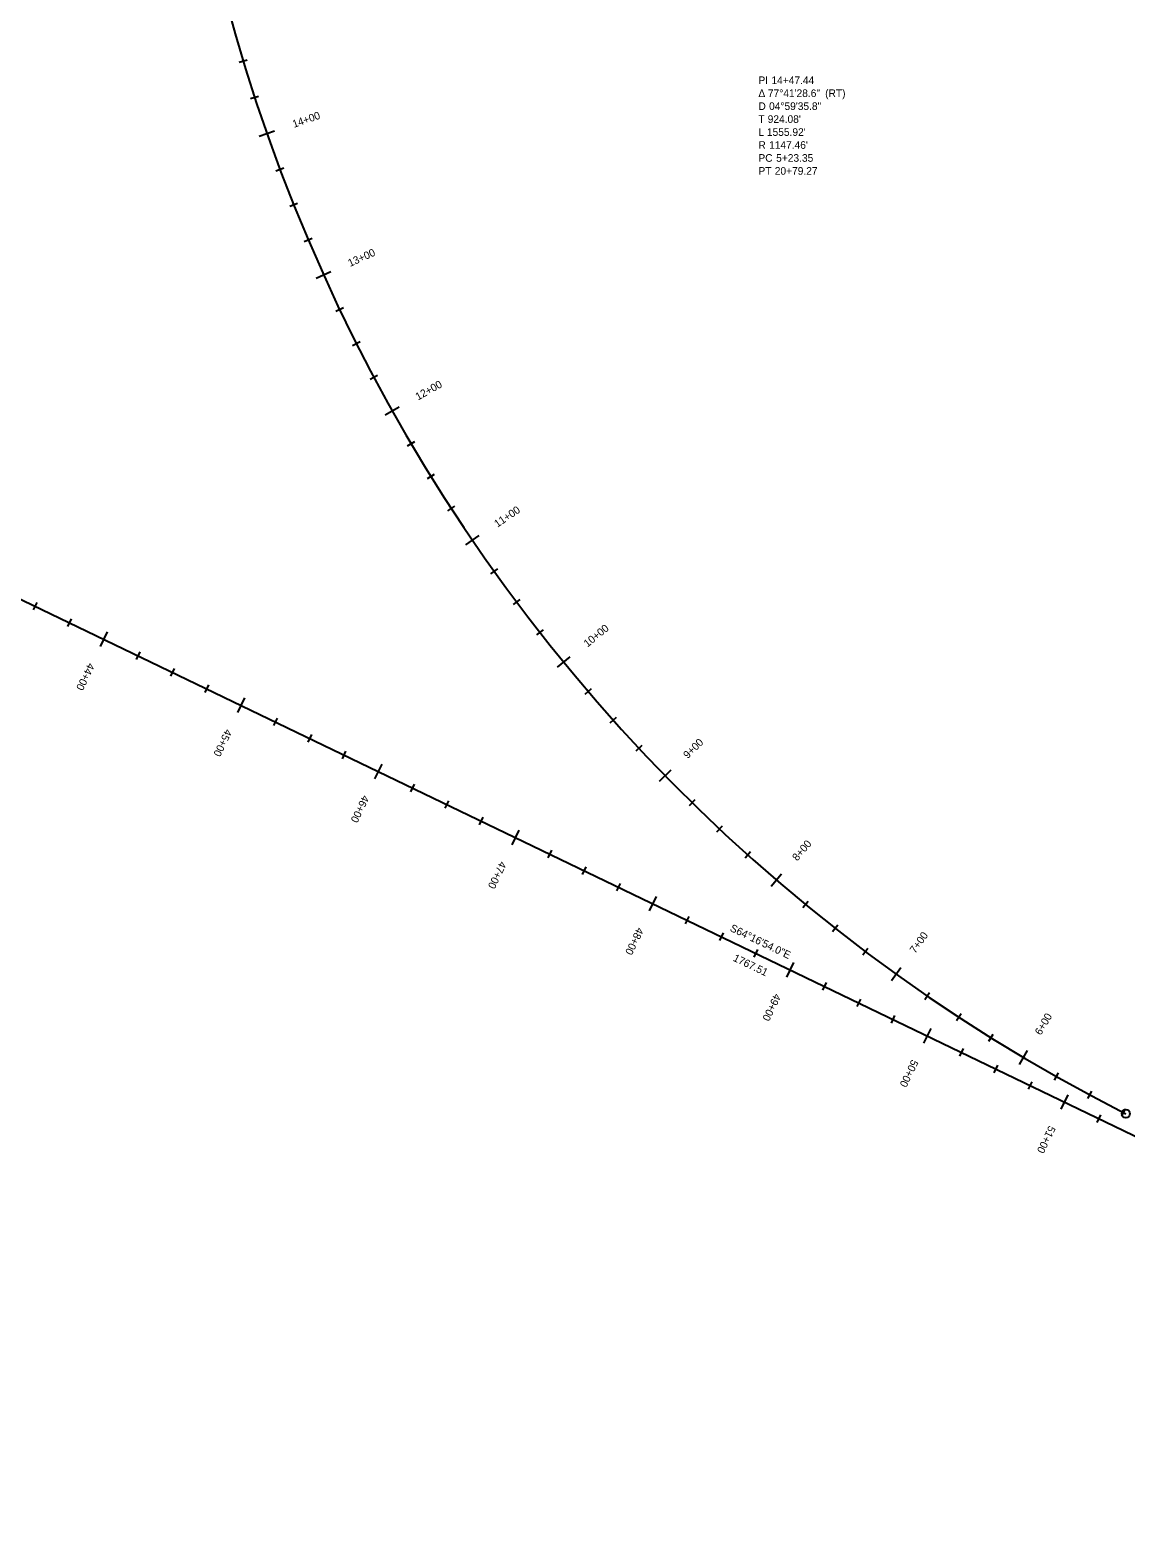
# Model space of a CAD drawing. Extents: x 2300830 to 2307917, y 756066 to 766359.
# Drawn here: x 2304246 to 2304965, y 761142 to 762132 of the extents above; entities that cross this region are included whole.
import ezdxf

# ---------------------------------------------------------------- set-up
doc = ezdxf.new("R2010")
doc.units = 0
for name, color, linetype in [('Default', 7, 'Continuous'), ('Draft_Bearing Label', 7, 'Continuous'), ('Draft_Curve Data Label', 7, 'Continuous'), ('Draft_Station Cardinal Points', 7, 'Continuous'), ('Draft_Station Labels Major', 7, 'Continuous'), ('Draft_Station Ticks Major', 7, 'Continuous'), ('Draft_Station Ticks Minor', 7, 'Continuous'), ('Geom_Baseline', 7, 'Continuous')]:
    doc.layers.add(name, color=color, linetype=linetype)

msp = doc.modelspace()

# ---------------------------------------------------------------- linework, layer by layer
at = {"layer": 'Default'}
msp.add_line((2303926.45, 761909.44), (2305518.87, 761142.43), dxfattribs=at)
for centre, radius, start, end in [((2294501.04, 766942.01), 10544.55, 331.835697, 340.516399), ((2305484.17, 762444.28), 1147.46, 165.42872, 243.12)]:
    msp.add_arc(centre, radius, start, end, dxfattribs=at)
at = {"layer": 'Draft_Station Cardinal Points'}
msp.add_line((2304965.38, 761420.8), (2304965.38, 761420.8), dxfattribs=at)
msp.add_circle((2304965.38, 761420.8), 2.67, dxfattribs=at)
at = {"layer": 'Draft_Station Ticks Major'}
for p, q in [((2304396.47, 762062.39), (2304406.49, 762065.9)), ((2304433.83, 761969.16), (2304443.51, 761973.54)), ((2304479.17, 761879.55), (2304488.43, 761884.75)), ((2304532.14, 761794.22), (2304540.91, 761800.2)), ((2304296.7, 761737.03), (2304292.09, 761727.46)), ((2304592.34, 761713.82), (2304600.55, 761720.55)), ((2304386.79, 761693.63), (2304382.18, 761684.07)), ((2304476.89, 761650.24), (2304472.28, 761640.67)), ((2304659.3, 761638.97), (2304666.9, 761646.39)), ((2304566.98, 761606.85), (2304562.37, 761597.28)), ((2304732.52, 761570.23), (2304739.45, 761578.28)), ((2304657.07, 761563.45), (2304652.47, 761553.88)), ((2304747.17, 761520.06), (2304742.56, 761510.49)), ((2304811.45, 761508.12), (2304817.65, 761516.75)), ((2304837.26, 761476.66), (2304832.65, 761467.09)), ((2304895.49, 761453.12), (2304900.91, 761462.25)), ((2304927.36, 761433.27), (2304922.75, 761423.7))]:
    msp.add_line(p, q, dxfattribs=at)
at = {"layer": 'Draft_Station Ticks Minor'}
for p, q in [((2304383.33, 762110.88), (2304388.62, 762112.48)), ((2304390.86, 762086.97), (2304396.1, 762088.69)), ((2304407.46, 762039.69), (2304412.63, 762041.63)), ((2304416.53, 762016.33), (2304421.65, 762018.38)), ((2304426.11, 761993.17), (2304431.18, 761995.33)), ((2304446.76, 761947.51), (2304451.74, 761949.89)), ((2304457.83, 761925.03), (2304462.76, 761927.52)), ((2304469.39, 761902.79), (2304474.26, 761905.39)), ((2304493.94, 761859.1), (2304498.69, 761861.91)), ((2304506.92, 761837.66), (2304511.61, 761840.58)), ((2304520.37, 761816.52), (2304524.99, 761819.53)), ((2304548.63, 761775.13), (2304553.12, 761778.34)), ((2304563.43, 761754.91), (2304567.85, 761758.22)), ((2304250.53, 761756.4), (2304248.14, 761751.43)), ((2304273.06, 761745.55), (2304270.66, 761740.58)), ((2304578.67, 761735.01), (2304583.01, 761738.42)), ((2304318.1, 761723.86), (2304315.71, 761718.88)), ((2304340.63, 761713.01), (2304338.23, 761708.03)), ((2304363.15, 761702.16), (2304360.75, 761697.19)), ((2304610.42, 761696.24), (2304614.62, 761699.83)), ((2304408.2, 761680.46), (2304405.8, 761675.49)), ((2304626.93, 761677.38), (2304631.04, 761681.06)), ((2304430.72, 761669.61), (2304428.33, 761664.64)), ((2304453.24, 761658.76), (2304450.85, 761653.79)), ((2304643.84, 761658.89), (2304647.87, 761662.66)), ((2304498.29, 761637.07), (2304495.9, 761632.09)), ((2304520.81, 761626.22), (2304518.42, 761621.24)), ((2304678.85, 761623.03), (2304682.71, 761626.97)), ((2304543.34, 761615.37), (2304540.94, 761610.4)), ((2304696.93, 761605.68), (2304700.71, 761609.71)), ((2304588.38, 761593.67), (2304585.99, 761588.7)), ((2304715.39, 761588.73), (2304719.08, 761592.84)), ((2304610.91, 761582.82), (2304608.51, 761577.85)), ((2304633.43, 761571.97), (2304631.04, 761567)), ((2304753.38, 761556.05), (2304756.89, 761560.32)), ((2304678.48, 761550.28), (2304676.08, 761545.3)), ((2304701, 761539.43), (2304698.61, 761534.46)), ((2304772.91, 761540.34), (2304776.32, 761544.68)), ((2304792.77, 761525.06), (2304796.09, 761529.47)), ((2304723.53, 761528.58), (2304721.13, 761523.61)), ((2304768.57, 761506.88), (2304766.18, 761501.91)), ((2304833.47, 761495.82), (2304836.59, 761500.37)), ((2304791.1, 761496.03), (2304788.7, 761491.06)), ((2304813.62, 761485.19), (2304811.22, 761480.21)), ((2304854.29, 761481.87), (2304857.31, 761486.49)), ((2304875.4, 761468.37), (2304878.32, 761473.06)), ((2304858.67, 761463.49), (2304856.27, 761458.51)), ((2304881.19, 761452.64), (2304878.79, 761447.67)), ((2304903.71, 761441.79), (2304901.32, 761436.82)), ((2304918.49, 761442.78), (2304921.21, 761447.59)), ((2304940.44, 761430.69), (2304943.05, 761435.56)), ((2304962.65, 761419.09), (2304965.16, 761424.01)), ((2304948.76, 761420.09), (2304946.36, 761415.12))]:
    msp.add_line(p, q, dxfattribs=at)
at = {"layer": 'Geom_Baseline'}
msp.add_line((2303926.45, 761909.44), (2305518.87, 761142.43), dxfattribs=at)
for centre, radius, start, end in [((2294501.04, 766942.01), 10544.55, 331.835697, 340.516399), ((2305484.17, 762444.28), 1147.46, 165.42872, 243.12)]:
    msp.add_arc(centre, radius, start, end, dxfattribs=at)

# ---------------------------------------------------------------- texts
at = {"layer": 'Draft_Bearing Label'}
for s, p in [('S64°16\'54.0"E', (2304705.08, 761540.93)), ('1767.51', (2304707.14, 761521.33))]:
    msp.add_text(s, height=5, rotation=334.28167, dxfattribs=at).set_placement(p)
at = {"layer": 'Draft_Curve Data Label'}
for s, p in [('PI ', (2304724.19, 762096.55)), ('14+47.44', (2304732.73, 762096.55)), (' (RT)', (2304766.14, 762088.05)), ('Δ ', (2304724.19, 762088.05)), ('D ', (2304724.19, 762079.55)), ('77°41\'28.6"', (2304730.41, 762088.05)), ('04°59\'35.8"', (2304731.18, 762079.55)), ('T ', (2304724.19, 762071.05)), ("924.08'", (2304730.28, 762071.05)), ('L ', (2304724.19, 762062.55)), ("1555.92'", (2304729.76, 762062.55)), ('R ', (2304724.19, 762054.05)), ("1147.46'", (2304731.18, 762054.05)), ('PC ', (2304724.19, 762045.55)), ('5+23.35', (2304735.84, 762045.55)), ('PT ', (2304724.19, 762037.05)), ('20+79.27', (2304734.94, 762037.05))]:
    msp.add_text(s, height=5, dxfattribs=at).set_placement(p)
at = {"layer": 'Draft_Station Labels Major'}
for s, rotation, p in [('14+00', 19.34639, (2304419.32, 762067.76)), ('13+00', 24.33968, (2304456.13, 761976.5)), ('12+00', 29.33296, (2304500.75, 761888.8)), ('11+00', 34.32625, (2304552.83, 761805.31)), ('10+00', 39.31953, (2304611.98, 761726.67)), ('44+00', 244.28167, (2304284.32, 761717.09)), ('45+00', 244.28167, (2304374.41, 761673.69)), ('9+00', 44.31282, (2304677.75, 761653.48)), ('46+00', 244.28167, (2304464.51, 761630.3)), ('8+00', 49.3061, (2304749.64, 761586.29)), ('47+00', 244.28167, (2304554.6, 761586.9)), ('48+00', 244.28167, (2304644.69, 761543.51)), ('7+00', 54.29939, (2304827.1, 761525.62)), ('49+00', 244.28167, (2304734.79, 761500.11)), ('6+00', 59.29267, (2304909.56, 761471.91)), ('50+00', 244.28167, (2304824.88, 761456.72)), ('51+00', 244.28167, (2304914.98, 761413.32))]:
    msp.add_text(s, height=5, rotation=rotation, dxfattribs=at).set_placement(p)

doc.saveas('drawing.dxf')
